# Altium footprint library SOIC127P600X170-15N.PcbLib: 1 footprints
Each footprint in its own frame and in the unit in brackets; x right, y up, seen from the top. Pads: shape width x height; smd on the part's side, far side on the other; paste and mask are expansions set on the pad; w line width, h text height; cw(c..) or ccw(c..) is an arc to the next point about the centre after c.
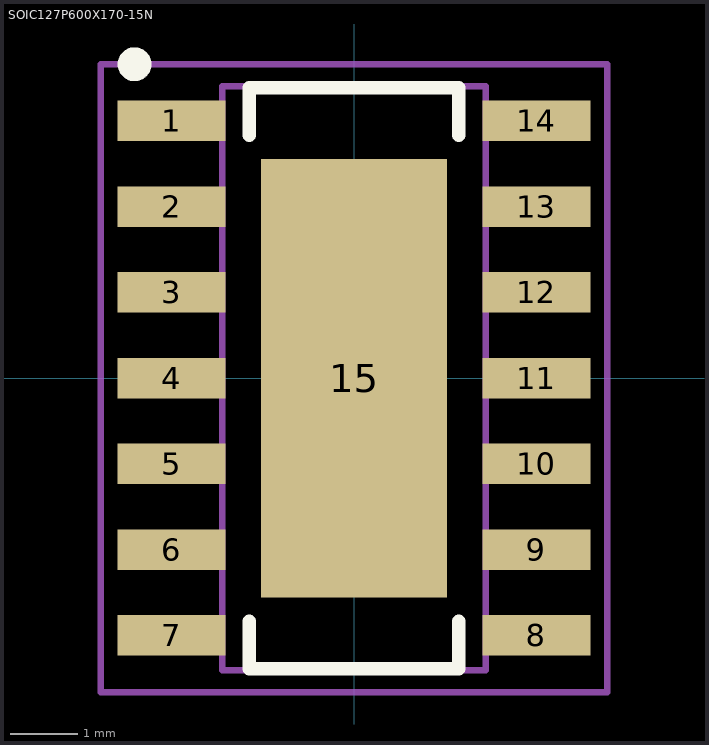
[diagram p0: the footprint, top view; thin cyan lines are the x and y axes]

## SOIC127P600X170-15N [mm] "SOIC,1.27mm pitch;14 pin,3.90mm W X 8.65mm L X 1.70mm H body (w/thermal tab)"
height 1.7
pads (15):
  rect 1.6x0.6 smd paste+0 mask+0: 1(-2.7,3.81) 2(-2.7,2.54) 3(-2.7,1.27) 4(-2.7,0) 5(-2.7,-1.27) 6(-2.7,-2.54) 7(-2.7,-3.81) 8(2.7,-3.81) 9(2.7,-2.54) 10(2.7,-1.27) 11(2.7,0) 12(2.7,1.27) 13(2.7,2.54) 14(2.7,3.81)
  rect 2.75x6.5 smd paste+0 mask+0: 15(0,0)
Top Overlay:
  circle w0.25: c-3.25,4.65 r0.125
  lines w0.2: -1.55,-3.6 -1.55,-4.3 1.55,-4.3 1.55,-3.6 ; -1.55,3.6 -1.55,4.3 1.55,4.3 1.55,3.6
M3 (ASY_Text_Top):
  text ".DESIGNATOR" at 0,0 h1.2
M13 (CMP_Body_OTL_Top):
  lines w0.1: -1.95,-4.325 -1.95,4.325 1.95,4.325 1.95,-4.325 -1.95,-4.325
M15 (CMP_Courtyard_Top):
  lines w0.1: -0.5,0 0.5,0 ; 0,-0.5 0,0.5 ; -3.75,-4.65 -3.75,4.65 3.75,4.65 3.75,-4.65 -3.75,-4.65
3D body: height 1.71, standoff 0, extent -3,-4.325 3,4.325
